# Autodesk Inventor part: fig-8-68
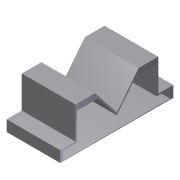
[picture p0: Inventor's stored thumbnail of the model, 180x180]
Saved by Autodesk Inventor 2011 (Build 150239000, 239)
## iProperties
Shininess: 77.0
Length Units: 11269
Angle Units: 11279
Time Units: 11290
Mass Units: 11283
Length Display Precision: 3
Angle Display Precision: 2
Created: 2002-01
Part Number: fig-8-68
Document SubType Name: Modeling
Designer: ***
Density: 1 g/cm^3
Density: 0.0
Volumn: 0.0
Area: 0.0
PropertySet Name: Model Information
Control State: 0
Master: False
Checked Out: False
Author: ***
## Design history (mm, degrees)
node "Sketch1"
sketch "Sketch2"
  geometry: L1 (0, 0)-(-14.184, 17.961); L2 (-14.184, 17.961)-(-26.987, 17.961); L3 (-26.987, 17.961)-(-26.987, -2.947); L4 (-26.987, -2.947)-(-36.842, -2.947); L5 (-36.842, -2.947)-(-36.842, -10.132); L6 (26.987, 17.961)-(26.987, -2.947); L7 (14.184, 17.961)-(26.987, 17.961); L8 (26.987, -2.947)-(36.842, -2.947); L9 (36.842, -10.132)-(-36.842, -10.132); L10 (36.842, -2.947)-(36.842, -10.132); L11 (0, 0)-(14.184, 17.961)
  constraints: 22 end point, 2 horizontal, 2 parallel, 1 perpendicular
extrude "Extrusion1" new body sketch "Sketch2" distance "d0" = 35; taper "d1" = 0 deg
shell "Shell3" dims "d8" = 4, "d9" = 4, "d10" = 2, "d11" = 2, "d12" = 0.5, "d13" = 1
body "Solid1"
